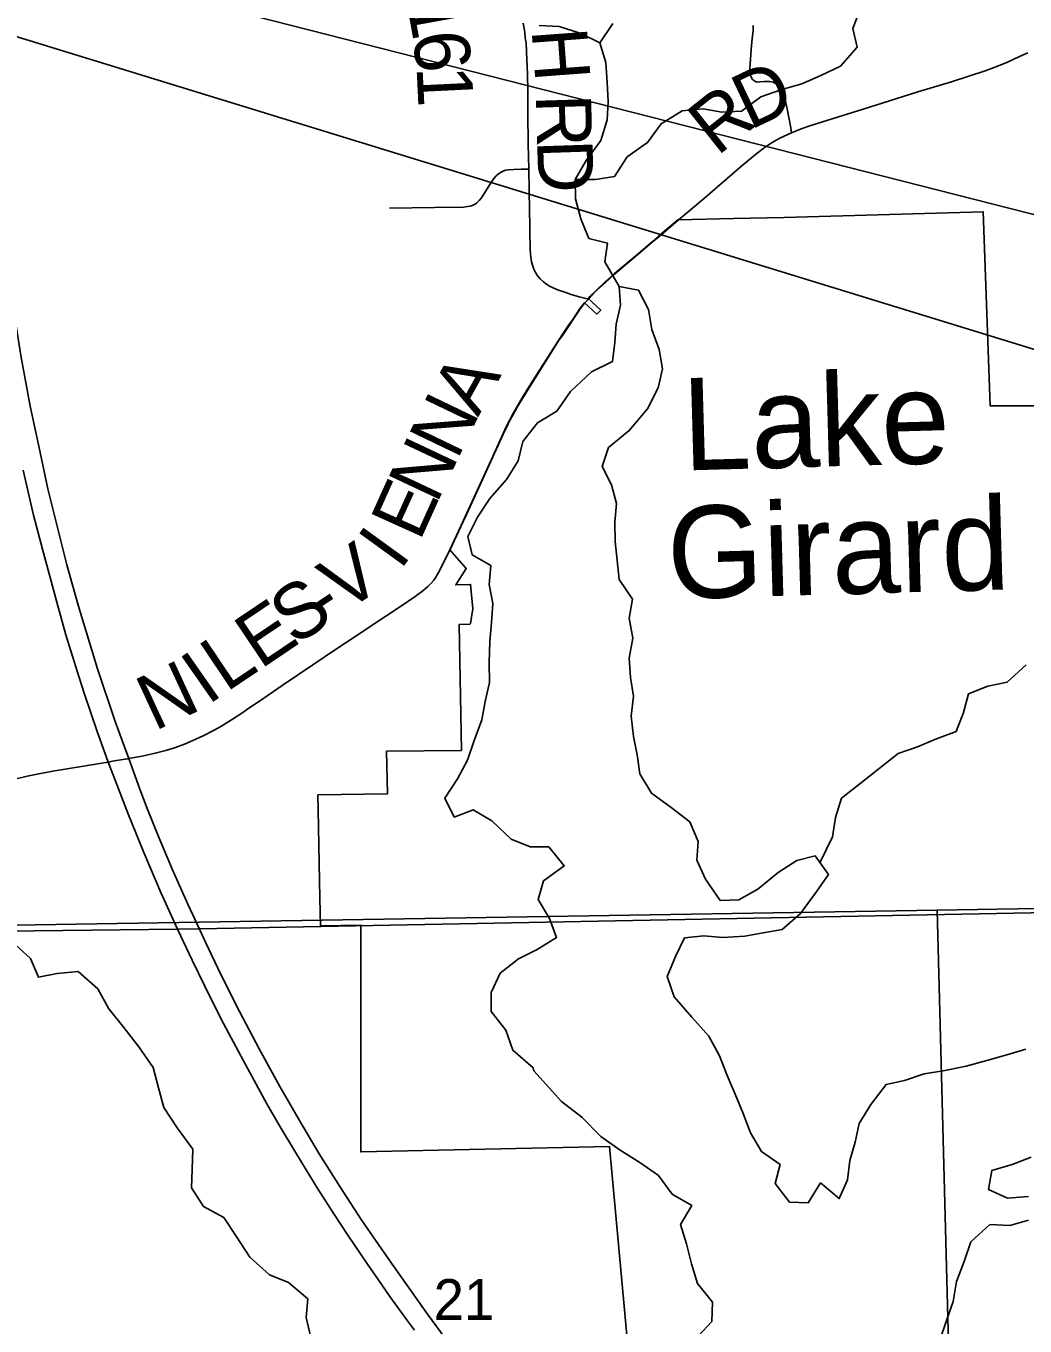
# Model space of a CAD drawing. Extents: x -6.4 to 34, y -4.2 to 22.
# Drawn here: x 7.115 to 8.141, y 15.496 to 16.831 of the extents above; entities that cross this region are included whole.
import ezdxf

# ---------------------------------------------------------------- set-up
doc = ezdxf.new("R2010")
doc.units = 0
for name, color, linetype in [('GM_X_Corporation', 7, 'Continuous'), ('GM_X_County_Road', 7, 'Continuous'), ('GM_X_County_Road_Text', 7, 'Continuous'), ('GM_X_Major_Lake', 7, 'Continuous'), ('GM_X_Major_Lake_Text', 7, 'Continuous'), ('GM_X_Minor_River', 7, 'Continuous'), ('GM_X_Section_Text', 7, 'Continuous'), ('GM_X_State_Route', 7, 'Continuous'), ('GM_X_Township_Road', 7, 'Continuous'), ('SH_Text', 7, 'Continuous')]:
    doc.layers.add(name, color=color, linetype=linetype)

msp = doc.modelspace()

# ---------------------------------------------------------------- linework, layer by layer
at = {"layer": 'GM_X_Corporation'}
for points in [[(7.0203, 17.4801), (7.0556, 16.0421), (7.0636, 15.9014), (7.2702, 15.904), (7.2926, 15.9044), (8.6815, 15.9311), (8.9, 15.9356), (8.9, 20.7065)], [(8.2531, 16.4413), (8.105, 16.4414), (8.0979, 16.6406), (7.8933, 16.6348), (7.8414, 16.6337), (7.7843, 16.6324), (7.7643, 16.6154), (7.7577, 16.6099), (7.7413, 16.5958), (7.7189, 16.577), (7.7096, 16.5687), (7.7005, 16.5601), (7.6938, 16.5536), (7.6922, 16.5515), (7.695, 16.5487), (7.6958, 16.548), (7.7049, 16.5397), (7.701, 16.5355), (7.6919, 16.5438), (7.6912, 16.5445), (7.6882, 16.5471), (7.6838, 16.5416), (7.6762, 16.5301), (7.6723, 16.5244), (7.6661, 16.5152), (7.6615, 16.5085), (7.6332, 16.4639), (7.6244, 16.4495), (7.619, 16.4405), (7.6143, 16.4324), (7.6111, 16.4263), (7.6083, 16.4204), (7.6046, 16.4128), (7.5923, 16.3856), (7.5669, 16.3303), (7.5612, 16.3178), (7.5499, 16.2936), (7.5668, 16.2744), (7.5561, 16.2575), (7.5713, 16.2579), (7.5735, 16.2329), (7.571, 16.2178), (7.5705, 16.2171), (7.5596, 16.2168), (7.5618, 16.0874), (7.485, 16.0866), (7.4858, 16.0428), (7.4145, 16.0418), (7.4148, 16.0263), (7.4164, 15.9357), (7.4169, 15.9073), (7.4586, 15.9081), (7.4585, 15.6751), (7.714, 15.6807), (7.7329, 15.4756)]]:
    msp.add_lwpolyline(points, dxfattribs=at)
for points in [[(7.1124, 14.1), (8.9, 14.1), (8.9, 15.9356), (8.6815, 15.9311), (7.2926, 15.9044), (7.2702, 15.904), (7.0636, 15.9014), (7.0744, 15.3393), (7.0897, 14.8536), (7.0948, 14.7153), (7.0983, 14.5939), (7.1017, 14.4646)], [(8.9, 15.1746), (8.9, 15.9375), (8.744, 15.9349), (8.175, 15.9256), (8.0507, 15.9235), (8.0705, 15.1646)], [(8.0507, 15.9235), (8.0705, 15.1646), (7.0784, 15.1559), (7.0606, 15.9074)]]:
    msp.add_lwpolyline(points, close=True, dxfattribs=at)
at = {"layer": 'GM_X_County_Road'}
msp.add_line((7.6884, 16.5466), (7.6924, 16.551), dxfattribs=at)
for points in [[(7.6924, 16.551), (7.6829, 16.5533), (7.6746, 16.5558), (7.6669, 16.5584), (7.6616, 16.5602), (7.6569, 16.562), (7.6524, 16.5643), (7.6491, 16.5663), (7.6461, 16.5686), (7.6429, 16.5717), (7.6404, 16.5746), (7.6379, 16.5784), (7.6363, 16.5818), (7.6352, 16.5848), (7.634, 16.5891), (7.6332, 16.5941), (7.6326, 16.6016), (7.6324, 16.6085), (7.6322, 16.6153), (7.632, 16.6258), (7.6317, 16.6421), (7.6314, 16.6632), (7.631, 16.6842), (7.6305, 16.7104), (7.6301, 16.7415), (7.6299, 16.7645), (7.6296, 16.7819), (7.6288, 16.8048), (7.6282, 16.8141), (7.6275, 16.8193), (7.6269, 16.8252), (7.6254, 16.8343)], [(7.7845, 16.6319), (7.8119, 16.655), (7.8504, 16.688), (7.8658, 16.7007), (7.873, 16.7062), (7.8783, 16.71), (7.8834, 16.7132), (7.8884, 16.716), (7.8934, 16.7184), (7.901, 16.7218), (7.9108, 16.7257), (7.9208, 16.7291), (7.9428, 16.7359), (7.9647, 16.7428), (7.9747, 16.746), (7.9942, 16.752), (8.0309, 16.7637), (8.0654, 16.7742), (8.1008, 16.7858), (8.1065, 16.7879), (8.1136, 16.7904), (8.1228, 16.7943), (8.1352, 16.8), (8.1436, 16.8039)], [(7.6924, 16.551), (7.694, 16.553), (7.7007, 16.5596), (7.7098, 16.5681), (7.7191, 16.5764), (7.7415, 16.5952), (7.7579, 16.6094), (7.7645, 16.6149), (7.7845, 16.6319)], [(7.5501, 16.293), (7.5614, 16.3173), (7.5671, 16.3297), (7.5925, 16.3851), (7.6048, 16.4123), (7.6085, 16.4198), (7.6113, 16.4258), (7.6145, 16.4318), (7.6192, 16.4399), (7.6246, 16.4489), (7.6334, 16.4633), (7.6617, 16.508), (7.6663, 16.5147), (7.6725, 16.5239), (7.6764, 16.5296), (7.6839, 16.541), (7.6884, 16.5466)], [(7.3411, 16.1293), (7.3587, 16.1412), (7.3778, 16.1541), (7.4092, 16.1754), (7.4334, 16.1917), (7.4532, 16.2047), (7.4702, 16.2162), (7.4994, 16.2353), (7.5142, 16.2455), (7.5221, 16.2514), (7.5273, 16.2558), (7.5307, 16.2592), (7.5335, 16.2624), (7.5355, 16.2655), (7.5383, 16.2703), (7.5501, 16.293)], [(7.22, 16.0791), (7.2257, 16.0801), (7.2339, 16.0817), (7.2473, 16.0846), (7.2581, 16.0875), (7.2681, 16.0906), (7.2774, 16.094), (7.286, 16.0976), (7.2967, 16.1025), (7.3072, 16.1079), (7.3147, 16.1121), (7.3258, 16.1189), (7.3361, 16.1258), (7.3411, 16.1293)], [(7.0558, 16.0416), (7.0588, 16.0428), (7.0698, 16.0473), (7.0786, 16.0505), (7.0904, 16.0543), (7.103, 16.0579), (7.1157, 16.061), (7.1261, 16.0632), (7.142, 16.0662), (7.1905, 16.0741), (7.1991, 16.0755), (7.2035, 16.0763), (7.2162, 16.0784), (7.2191, 16.0789), (7.22, 16.0791)]]:
    msp.add_lwpolyline(points, dxfattribs=at)
at = {"layer": 'GM_X_Major_Lake'}
msp.add_line((7.6362, 15.7586), (7.6648, 15.7269), dxfattribs=at)
for points in [[(7.8432, 15.7345), (7.8349, 15.7535), (7.8271, 15.7737), (7.8159, 15.7942), (7.7986, 15.8137), (7.7805, 15.8343), (7.7731, 15.8552), (7.7819, 15.876), (7.7911, 15.895), (7.8108, 15.8972), (7.8305, 15.8952), (7.8529, 15.8966), (7.8718, 15.9003), (7.8912, 15.9036), (7.9102, 15.9199), (7.9251, 15.9407), (7.9388, 15.96), (7.9253, 15.9791), (7.9064, 15.9746), (7.8874, 15.9621), (7.8664, 15.9451), (7.847, 15.9342), (7.8277, 15.9335), (7.8127, 15.9553), (7.8038, 15.9747), (7.805, 15.994), (7.7964, 16.0142), (7.7772, 16.0287), (7.7572, 16.0436), (7.7452, 16.0634), (7.7423, 16.0828), (7.7387, 16.1018), (7.7362, 16.1227), (7.7386, 16.1432), (7.7356, 16.1622), (7.7343, 16.1823), (7.7378, 16.2028), (7.7341, 16.2233), (7.7377, 16.2427), (7.7238, 16.2629), (7.722, 16.2826), (7.7199, 16.302), (7.7196, 16.3218), (7.7212, 16.3411), (7.7161, 16.3601), (7.7063, 16.3792), (7.7129, 16.3985), (7.7342, 16.4159), (7.7529, 16.4382), (7.764, 16.4598), (7.7683, 16.4792), (7.765, 16.4993), (7.7576, 16.5198), (7.7539, 16.5404), (7.7438, 16.5602), (7.7238, 16.564), (7.7252, 16.5447), (7.7209, 16.5253), (7.7196, 16.5063), (7.7172, 16.487), (7.6956, 16.4761), (7.6739, 16.456), (7.6597, 16.436), (7.64, 16.4239), (7.6251, 16.4046), (7.6201, 16.3849), (7.6082, 16.3656), (7.591, 16.3463), (7.5784, 16.3269), (7.5684, 16.3072), (7.5729, 16.2882), (7.5921, 16.2775), (7.5905, 16.2578), (7.5941, 16.2384), (7.5929, 16.219), (7.5912, 16.1993), (7.5904, 16.1776), (7.5906, 16.1571), (7.5863, 16.1378), (7.5828, 16.1188), (7.5747, 16.0968), (7.5681, 16.0775), (7.5578, 16.0582), (7.5448, 16.0385), (7.5545, 16.0191), (7.5739, 16.0266), (7.5931, 16.0151), (7.6131, 15.9964), (7.6323, 15.9883), (7.6516, 15.9886), (7.6674, 15.9688), (7.6461, 15.9537), (7.6407, 15.9344), (7.6523, 15.915), (7.6594, 15.8952), (7.6396, 15.8831), (7.6206, 15.8733), (7.6016, 15.8586), (7.5924, 15.8389), (7.5923, 15.8195), (7.6073, 15.8001)], [(7.6073, 15.8001), (7.6147, 15.7795), (7.6355, 15.7616), (7.6362, 15.7586)], [(8.1418, 15.7806), (8.1221, 15.775), (8.1016, 15.769), (8.0803, 15.7634), (8.0568, 15.7586), (8.0371, 15.7553), (8.017, 15.7485), (7.9981, 15.7444), (7.9824, 15.724), (7.9706, 15.7043), (7.9663, 15.6853), (7.9609, 15.6664), (7.9585, 15.6466), (7.95, 15.6273), (7.9308, 15.6433), (7.9182, 15.6229), (7.8989, 15.6237), (7.8842, 15.6428), (7.8893, 15.6621), (7.87, 15.6755), (7.8588, 15.6949), (7.8514, 15.7147), (7.8432, 15.7345)], [(7.6648, 15.7269), (7.6855, 15.7109), (7.7051, 15.691), (7.725, 15.6769), (7.745, 15.6643), (7.7643, 15.6509), (7.7782, 15.6319), (7.7985, 15.62), (7.787, 15.6007), (7.793, 15.5809), (7.7982, 15.5604), (7.8045, 15.5402), (7.8199, 15.5208), (7.819, 15.501), (7.8011, 15.4814)], [(8.1443, 15.6295), (8.1227, 15.6277), (8.1034, 15.6365), (8.1066, 15.6562), (8.1278, 15.6622), (8.1472, 15.6697)], [(8.0532, 15.4818), (8.0602, 15.5019), (8.0671, 15.5216), (8.0703, 15.5421), (8.0787, 15.5637), (8.0853, 15.583), (8.1047, 15.6008), (8.1251, 15.5996), (8.1445, 15.6052)]]:
    msp.add_lwpolyline(points, dxfattribs=at)
at = {"layer": 'GM_X_Minor_River'}
for points in [[(7.7238, 16.564), (7.7092, 16.5892), (7.7119, 16.6085), (7.6927, 16.6132), (7.6845, 16.6333), (7.6789, 16.6539), (7.6787, 16.6736), (7.6995, 16.6739), (7.7192, 16.6769), (7.7322, 16.6969), (7.7531, 16.7117), (7.7669, 16.731), (7.7885, 16.7442), (7.8101, 16.7464), (7.8294, 16.7429), (7.8495, 16.7439), (7.8693, 16.7586), (7.8901, 16.7658), (7.9114, 16.7721), (7.9311, 16.7804), (7.9512, 16.7902), (7.9684, 16.8095), (7.964, 16.8289), (7.9713, 16.8478)], [(7.6787, 16.6736), (7.6901, 16.6933), (7.705, 16.7138), (7.7116, 16.735), (7.7125, 16.754), (7.7115, 16.7734), (7.7101, 16.7939), (7.7042, 16.814), (7.7175, 16.8341)], [(7.7042, 16.814), (7.6838, 16.824), (7.6622, 16.8309), (7.6418, 16.8318)], [(7.9302, 15.9722), (7.9429, 15.9987), (7.946, 16.0185), (7.9522, 16.0386), (7.9712, 16.0533), (7.991, 16.0688), (8.0104, 16.0843), (8.0305, 16.091), (8.0499, 16.0993), (8.07, 16.1068), (8.0777, 16.1265), (8.0827, 16.1455), (8.1028, 16.1534), (8.1226, 16.1575), (8.142, 16.1752)], [(7.407, 15.4847), (7.4025, 15.5052), (7.4042, 15.5242), (7.3842, 15.541), (7.3646, 15.549), (7.3446, 15.567), (7.3304, 15.5887), (7.3176, 15.6077), (7.2968, 15.6192), (7.2845, 15.6382), (7.2853, 15.6572), (7.2859, 15.6781), (7.2697, 15.6998), (7.2562, 15.7208), (7.2507, 15.7409), (7.2451, 15.7618), (7.2305, 15.7832), (7.2151, 15.803), (7.1997, 15.822), (7.1884, 15.8426), (7.1681, 15.8605), (7.1465, 15.8584), (7.1275, 15.8546), (7.1193, 15.8737), (7.0998, 15.8912)]]:
    msp.add_lwpolyline(points, dxfattribs=at)
at = {"layer": 'GM_X_State_Route'}
for points in [[(7.2156, 16.091), (7.2133, 16.0975), (7.206, 16.117), (7.188, 16.1712), (7.168, 16.2365), (7.1566, 16.2779), (7.137, 16.356), (7.1276, 16.3999), (7.1189, 16.4411), (7.1092, 16.4931), (7.1027, 16.5343), (7.0988, 16.5627), (7.0937, 16.6018), (7.0894, 16.6395), (7.0855, 16.6813), (7.0818, 16.7279), (7.08, 16.7594), (7.0776, 16.8125), (7.0772, 16.8681)], [(7.2704, 15.9034), (7.2685, 15.9077), (7.2532, 15.9417), (7.2355, 15.9828), (7.2199, 16.0214), (7.2044, 16.0614), (7.1991, 16.0755), (7.1969, 16.0811), (7.1877, 16.1069), (7.1746, 16.1451), (7.169, 16.1622), (7.1556, 16.2062), (7.1462, 16.2398), (7.1313, 16.294), (7.1223, 16.3289), (7.1117, 16.3752)], [(7.2928, 15.9039), (7.2807, 15.9295), (7.2651, 15.9648), (7.2514, 15.9974), (7.2391, 16.028), (7.2314, 16.0477), (7.22, 16.0791), (7.2156, 16.091)], [(7.5136, 15.4921), (7.5066, 15.5016), (7.4884, 15.5268), (7.4762, 15.544), (7.4653, 15.5598), (7.4451, 15.5897), (7.4308, 15.6116), (7.4138, 15.6383), (7.3985, 15.6631), (7.3907, 15.6759), (7.3758, 15.701), (7.3621, 15.7246), (7.3378, 15.7687), (7.3174, 15.8071), (7.3047, 15.832), (7.2851, 15.8722), (7.2704, 15.9034)], [(7.7919, 15.1683), (7.7596, 15.2089), (7.7218, 15.2575), (7.6979, 15.288), (7.6907, 15.2975), (7.6847, 15.3052), (7.6685, 15.3264), (7.6298, 15.376), (7.5752, 15.4449), (7.5588, 15.4663), (7.5453, 15.4839), (7.527, 15.5087), (7.4882, 15.5633), (7.4596, 15.6046), (7.4369, 15.6395), (7.4158, 15.6732), (7.3954, 15.7074), (7.3753, 15.7425), (7.354, 15.7812), (7.334, 15.8192), (7.3147, 15.8575), (7.2988, 15.8905), (7.2928, 15.9039)]]:
    msp.add_lwpolyline(points, dxfattribs=at)
at = {"layer": 'GM_X_Township_Road'}
for points in [[(7.901, 16.7218), (7.9001, 16.7269), (7.8981, 16.7374), (7.896, 16.7481), (7.8943, 16.7555), (7.8924, 16.7627), (7.8913, 16.7656), (7.8905, 16.7672), (7.8891, 16.7693), (7.8883, 16.7702), (7.8873, 16.771), (7.8858, 16.772), (7.8836, 16.773), (7.882, 16.7736), (7.8803, 16.774), (7.8784, 16.7743), (7.8754, 16.7744), (7.8728, 16.7743), (7.8684, 16.7739), (7.8669, 16.7738), (7.8657, 16.7739), (7.8648, 16.7741), (7.864, 16.7744), (7.8633, 16.7749), (7.8624, 16.7754), (7.8617, 16.776), (7.861, 16.7766), (7.8604, 16.7773), (7.86, 16.7781), (7.8591, 16.7797), (7.8586, 16.7814), (7.8583, 16.7838), (7.8583, 16.7882), (7.8589, 16.7969), (7.8596, 16.8073), (7.8607, 16.8186), (7.8615, 16.8265), (7.8616, 16.8282), (7.8616, 16.8294), (7.8616, 16.8307), (7.8613, 16.832)], [(7.4881, 16.6444), (7.5341, 16.645), (7.5639, 16.6455), (7.5682, 16.6459), (7.5713, 16.6465), (7.5736, 16.6473), (7.5758, 16.6485), (7.5778, 16.6499), (7.58, 16.6521), (7.5823, 16.655), (7.5918, 16.6696), (7.5952, 16.6748), (7.5976, 16.6776), (7.5999, 16.6797), (7.602, 16.6811), (7.6048, 16.6824), (7.6071, 16.6832), (7.6102, 16.6837), (7.6158, 16.6841), (7.6232, 16.6842), (7.631, 16.6842)]]:
    msp.add_lwpolyline(points, dxfattribs=at)
at = {"layer": 'SH_Text'}
msp.add_lwpolyline([(9.3252, 16.3385), (9.3252, 16.1385), (5.5217, 17.3069)], close=True, dxfattribs=at)

# ---------------------------------------------------------------- texts
at = {"layer": 'GM_X_County_Road_Text'}
for s, rotation, p in [('1', 280.3021, (7.5053, 16.8567)), ('6', 277.258, (7.5114, 16.823)), ('H', 274.266, (7.6339, 16.8275)), ('1', 272.8008, (7.5157, 16.7894)), ('D', 25.3366, (7.8581, 16.7242)), ('R', 271.7371, (7.6381, 16.7608)), ('R', 38.4992, (7.8245, 16.697)), ('D', 271.8925, (7.6395, 16.714)), ('A', 60.8683, (7.5788, 16.4291)), ('N', 64.3237, (7.5575, 16.3848)), ('N', 64.8084, (7.5363, 16.3397)), ('E', 65.7027, (7.5189, 16.3012)), ('I', 54.0608, (7.4989, 16.2714)), ('V', 33.9555, (7.4418, 16.2284)), ('S', 33.9141, (7.3906, 16.194)), ('-', 33.9087, (7.4224, 16.2154)), ('E', 33.9165, (7.3553, 16.1703)), ('L', 33.9082, (7.3201, 16.1466)), ('I', 34.9387, (7.3012, 16.1333)), ('N', 24.9031, (7.2464, 16.1069))]:
    msp.add_text(s, height=0.0568, rotation=rotation, dxfattribs=at).set_placement(p)
at = {"layer": 'GM_X_Major_Lake_Text'}
for s, rotation, p in [('Lake', 1.6282, (7.79, 16.3749)), ('Girard', 1.6276, (7.7745, 16.2429))]:
    msp.add_text(s, height=0.09474, rotation=rotation, dxfattribs=at).set_placement(p)
at = {"layer": 'GM_X_Section_Text'}
msp.add_text('21', height=0.04186, rotation=0, dxfattribs=at).set_placement((7.5333, 15.5027))

doc.saveas('drawing.dxf')
